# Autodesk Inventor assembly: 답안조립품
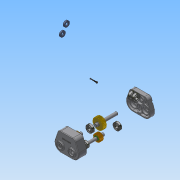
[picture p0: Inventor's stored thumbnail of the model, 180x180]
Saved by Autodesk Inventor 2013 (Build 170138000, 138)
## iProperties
Created: 2014-12
Part Number: 답안조립품
Document SubType Name: Assembly
Designer: Administrator
Author: Administrator
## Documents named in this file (14)
- C:\Users\Administrator\Desktop\441209V1042\441209V1042\답안조립품.iam
- C:\Users\Administrator\Desktop\441209V1042\441209V1042\본체.ipt
- C:\Users\Administrator\Desktop\441209V1042\441209V1042\M 5 x 35.ipt
- C:\Users\Administrator\Desktop\441209V1042\441209V1042\멈춤링.ipt
- C:\Users\Administrator\Desktop\441209V1042\441209V1042\메인기어.ipt
- C:\Users\Administrator\Desktop\441209V1042\441209V1042\메인축.ipt
- C:\Users\Administrator\Desktop\441209V1042\441209V1042\베어링- 6202.ipt
- C:\Users\Administrator\Desktop\441209V1042\441209V1042\베어링- 6203.ipt
- C:\Users\Administrator\Desktop\441209V1042\441209V1042\서브기어.ipt
- C:\Users\Administrator\Desktop\441209V1042\441209V1042\서브축.ipt
- C:\Users\Administrator\Desktop\441209V1042\441209V1042\오일시일-D-15.ipt
- C:\Users\Administrator\Desktop\441209V1042\441209V1042\오일시일-D-17.ipt
- C:\Users\Administrator\Desktop\441209V1042\441209V1042\커버.ipt
- C:\Users\Administrator\Desktop\441209V1042\441209V1042\키5x5.ipt
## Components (9 placed, 6 different names)
1. KS B 1003 - 미터 M 5 x 35:1
2. KS B 1336 17 x 1:1
3. KS B 2023 6202 - 15 x 35 x 11:1
4. KS B 2023 6203 - 17 x 40 x 12:1
5. KS B 2804 D D - 15 30 7:1
6. KS B 2804 D D - 17 30 8:1
7. KS B 2023 6203 - 17 x 40 x 12:2
8. KS B 2023 6203 - 17 x 40 x 12:3
9. KS B 2023 6203 - 17 x 40 x 12:4
